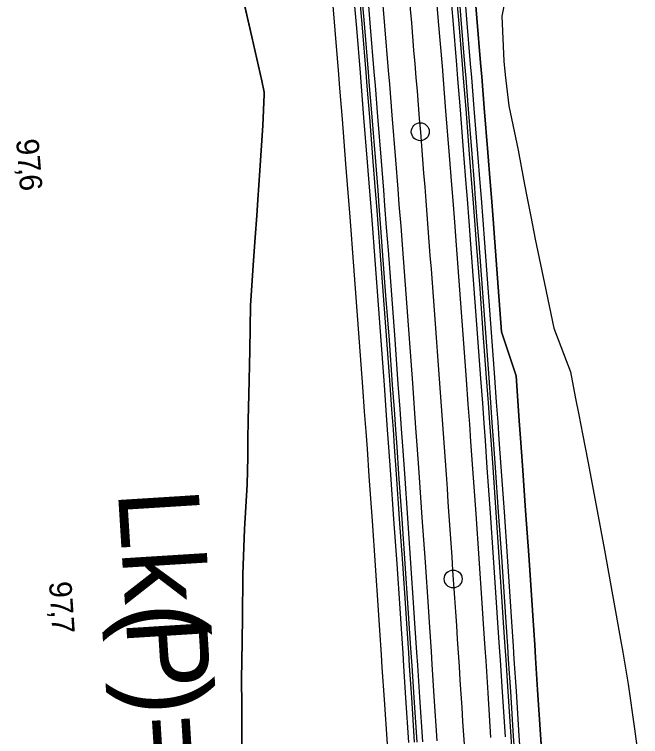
# Model space of a CAD drawing. Extents: x -678487 to -674601, y -1104811 to -1093295.
# Drawn here: x -677608.1 to -677468.4, y -1094531.8 to -1094370.8 of the extents above; entities that cross this region are included whole.
import ezdxf

# ---------------------------------------------------------------- set-up
doc = ezdxf.new("R2010")
doc.units = 0
for name, color, linetype in [('SOxxxxxx_Koleje_param další_Popis10', 7, 'Continuous'), ('SOxxxxxx_Osa_bod_P', 7, 'Continuous'), ('SOxxxxxx_Staničení_Popis', 7, 'Continuous'), ('SOxxxxxx_ŽSp_hrana', 7, 'Continuous'), ('SOxxxxxx_ŽSp_odvodnění', 7, 'Continuous'), ('SOxxxxxx_ŽSp_zářez_hrana', 7, 'Continuous'), ('SOxxxxxx_ŽSp_zářez_plocha', 7, 'Continuous')]:
    doc.layers.add(name, color=color, linetype=linetype)

msp = doc.modelspace()

# ---------------------------------------------------------------- linework, layer by layer
at = {"layer": 'SOxxxxxx_Osa_bod_P'}
msp.add_open_spline([(-677520.55, -1094360.39), (-677517.78, -1094392.94), (-677512.67, -1094458.09), (-677506.24, -1094555.89), (-677500.39, -1094653.74), (-677496.83, -1094718.98), (-677495.03, -1094751.61)], degree=3, dxfattribs=at)
at = {"layer": 'SOxxxxxx_Staničení_Popis'}
for p, q in [((-677517.54, -1094396.91), (-677517.54, -1094396.91)), ((-677510.2, -1094496.64), (-677510.2, -1094496.64))]:
    msp.add_line(p, q, dxfattribs=at)
for centre in [(-677517.54, -1094396.91), (-677510.2, -1094496.64)]:
    msp.add_circle(centre, 2, dxfattribs=at)
at = {"layer": 'SOxxxxxx_ŽSp_hrana'}
for p, q in [((-677526.33, -1094363.35), (-677525.49, -1094373.31)), ((-677525.49, -1094373.31), (-677524.67, -1094383.27)), ((-677524.67, -1094383.27), (-677524.42, -1094386.32)), ((-677524.42, -1094386.32), (-677523.86, -1094393.22)), ((-677523.86, -1094393.22), (-677523.07, -1094403.18)), ((-677523.07, -1094403.18), (-677522.56, -1094409.7)), ((-677522.56, -1094409.7), (-677522.29, -1094413.14)), ((-677522.29, -1094413.14), (-677521.91, -1094418)), ((-677521.91, -1094418), (-677521.52, -1094423.11)), ((-677521.52, -1094423.11), (-677520.77, -1094433.07)), ((-677520.77, -1094433.07), (-677520.03, -1094443.03)), ((-677520.03, -1094443.03), (-677519.3, -1094453)), ((-677519.3, -1094453), (-677518.89, -1094458.53)), ((-677518.89, -1094458.53), (-677518.58, -1094462.96)), ((-677518.58, -1094462.96), (-677518.3, -1094466.83)), ((-677518.3, -1094466.83), (-677517.87, -1094472.93)), ((-677517.87, -1094472.93), (-677517.17, -1094482.9)), ((-677517.17, -1094482.9), (-677516.48, -1094492.87)), ((-677516.48, -1094492.87), (-677515.81, -1094502.84)), ((-677515.81, -1094502.84), (-677515.5, -1094507.38)), ((-677515.5, -1094507.38), (-677515.14, -1094512.81)), ((-677515.14, -1094512.81), (-677514.95, -1094515.69)), ((-677514.95, -1094515.69), (-677514.48, -1094522.78)), ((-677514.48, -1094522.78), (-677513.83, -1094532.75))]:
    msp.add_line(p, q, dxfattribs=at)
msp.add_lwpolyline([(-677514.35, -1094362.34), (-677513.52, -1094372.31), (-677512.69, -1094382.29), (-677512.44, -1094385.35), (-677511.88, -1094392.26), (-677511.09, -1094402.24), (-677510.57, -1094408.77), (-677510.31, -1094412.22), (-677509.93, -1094417.08), (-677509.54, -1094422.2), (-677508.78, -1094432.18), (-677508.04, -1094442.16), (-677507.31, -1094452.14), (-677506.9, -1094457.68), (-677506.59, -1094462.12), (-677506.31, -1094466), (-677505.88, -1094472.11), (-677505.18, -1094482.09), (-677504.49, -1094492.07), (-677503.81, -1094502.06), (-677503.51, -1094506.61), (-677503.14, -1094512.04), (-677502.95, -1094514.93), (-677502.49, -1094522.03), (-677501.84, -1094532.02)], dxfattribs=at)
at = {"layer": 'SOxxxxxx_ŽSp_odvodnění'}
for p, q in [((-677509.87, -1094361.96), (-677509.03, -1094371.94)), ((-677509.32, -1094361.91), (-677508.48, -1094371.89)), ((-677531.36, -1094363.78), (-677530.53, -1094373.73)), ((-677530.81, -1094363.73), (-677529.98, -1094373.68)), ((-677509.03, -1094371.94), (-677508.21, -1094381.92)), ((-677508.48, -1094371.89), (-677507.66, -1094381.88)), ((-677530.53, -1094373.73), (-677529.71, -1094383.68)), ((-677529.98, -1094373.68), (-677529.16, -1094383.63)), ((-677508.21, -1094381.92), (-677507.96, -1094384.99)), ((-677507.66, -1094381.88), (-677507.41, -1094384.94)), ((-677529.71, -1094383.68), (-677529.46, -1094386.73)), ((-677529.16, -1094383.63), (-677528.91, -1094386.69)), ((-677507.96, -1094384.99), (-677507.4, -1094391.9)), ((-677507.41, -1094384.94), (-677506.85, -1094391.86)), ((-677529.46, -1094386.73), (-677528.9, -1094393.63)), ((-677528.91, -1094386.69), (-677528.35, -1094393.58)), ((-677507.4, -1094391.9), (-677506.6, -1094401.89)), ((-677506.85, -1094391.86), (-677506.05, -1094401.85)), ((-677528.35, -1094393.58), (-677527.56, -1094403.54)), ((-677528.9, -1094393.63), (-677528.1, -1094403.58)), ((-677506.6, -1094401.89), (-677506.09, -1094408.42)), ((-677506.05, -1094401.85), (-677505.54, -1094408.38)), ((-677528.1, -1094403.58), (-677527.59, -1094410.09)), ((-677527.56, -1094403.54), (-677527.04, -1094410.05)), ((-677506.09, -1094408.42), (-677505.82, -1094411.87)), ((-677505.54, -1094408.38), (-677505.27, -1094411.83)), ((-677527.59, -1094410.09), (-677527.32, -1094413.53)), ((-677527.04, -1094410.05), (-677526.78, -1094413.49)), ((-677505.82, -1094411.87), (-677505.44, -1094416.74)), ((-677505.27, -1094411.83), (-677504.89, -1094416.7)), ((-677527.32, -1094413.53), (-677526.95, -1094418.38)), ((-677526.78, -1094413.49), (-677526.4, -1094418.34)), ((-677505.44, -1094416.74), (-677505.05, -1094421.86)), ((-677504.89, -1094416.7), (-677504.5, -1094421.82)), ((-677526.95, -1094418.38), (-677526.56, -1094423.49)), ((-677526.4, -1094418.34), (-677526.01, -1094423.44)), ((-677505.05, -1094421.86), (-677504.29, -1094431.85)), ((-677504.5, -1094421.82), (-677503.74, -1094431.81)), ((-677526.56, -1094423.49), (-677525.8, -1094433.44)), ((-677526.01, -1094423.44), (-677525.26, -1094433.4)), ((-677504.29, -1094431.85), (-677503.55, -1094441.83)), ((-677503.74, -1094431.81), (-677503, -1094441.79)), ((-677525.8, -1094433.44), (-677525.06, -1094443.4)), ((-677525.26, -1094433.4), (-677524.51, -1094443.36)), ((-677503.55, -1094441.83), (-677502.82, -1094451.82)), ((-677503, -1094441.79), (-677502.27, -1094451.78)), ((-677525.06, -1094443.4), (-677524.33, -1094453.36)), ((-677524.51, -1094443.36), (-677523.78, -1094453.32)), ((-677502.82, -1094451.82), (-677502.42, -1094457.36)), ((-677502.27, -1094451.78), (-677501.87, -1094457.32)), ((-677524.33, -1094453.36), (-677523.93, -1094458.88)), ((-677523.78, -1094453.32), (-677523.38, -1094458.84)), ((-677502.42, -1094457.36), (-677502.1, -1094461.81)), ((-677501.87, -1094457.32), (-677501.55, -1094461.77)), ((-677523.93, -1094458.88), (-677523.61, -1094463.32)), ((-677523.38, -1094458.84), (-677523.07, -1094463.28)), ((-677502.1, -1094461.81), (-677501.82, -1094465.69)), ((-677501.55, -1094461.77), (-677501.27, -1094465.65)), ((-677523.61, -1094463.32), (-677523.34, -1094467.18)), ((-677523.07, -1094463.28), (-677522.79, -1094467.14)), ((-677501.82, -1094465.69), (-677501.39, -1094471.8)), ((-677501.27, -1094465.65), (-677500.84, -1094471.76)), ((-677523.34, -1094467.18), (-677522.91, -1094473.28)), ((-677522.79, -1094467.14), (-677522.36, -1094473.24)), ((-677501.39, -1094471.8), (-677500.69, -1094481.79)), ((-677500.84, -1094471.76), (-677500.14, -1094481.75)), ((-677522.91, -1094473.28), (-677522.21, -1094483.24)), ((-677522.36, -1094473.24), (-677521.66, -1094483.2)), ((-677500.69, -1094481.79), (-677500, -1094491.78)), ((-677500.14, -1094481.75), (-677499.45, -1094491.74)), ((-677522.21, -1094483.24), (-677521.52, -1094493.2)), ((-677521.66, -1094483.2), (-677520.97, -1094493.16)), ((-677500, -1094491.78), (-677499.32, -1094501.77)), ((-677499.45, -1094491.74), (-677498.77, -1094501.73)), ((-677521.52, -1094493.2), (-677520.85, -1094503.16)), ((-677520.97, -1094493.16), (-677520.3, -1094503.13)), ((-677499.32, -1094501.77), (-677499.02, -1094506.32)), ((-677498.77, -1094501.73), (-677498.47, -1094506.28)), ((-677520.85, -1094503.16), (-677520.54, -1094507.7)), ((-677520.3, -1094503.13), (-677519.99, -1094507.67)), ((-677499.02, -1094506.32), (-677498.65, -1094511.76)), ((-677498.47, -1094506.28), (-677498.11, -1094511.72)), ((-677520.54, -1094507.7), (-677520.18, -1094513.13)), ((-677519.99, -1094507.67), (-677519.63, -1094513.09)), ((-677498.65, -1094511.76), (-677498.46, -1094514.65)), ((-677498.11, -1094511.72), (-677497.91, -1094514.61)), ((-677520.18, -1094513.13), (-677519.99, -1094516.01)), ((-677519.63, -1094513.09), (-677519.44, -1094515.98)), ((-677519.44, -1094515.98), (-677518.97, -1094523.06)), ((-677498.46, -1094514.65), (-677497.99, -1094521.75)), ((-677497.91, -1094514.61), (-677497.45, -1094521.71)), ((-677519.99, -1094516.01), (-677519.52, -1094523.1)), ((-677497.99, -1094521.75), (-677497.34, -1094531.74)), ((-677497.45, -1094521.71), (-677496.8, -1094531.71)), ((-677519.52, -1094523.1), (-677518.87, -1094533.06)), ((-677518.97, -1094523.06), (-677518.33, -1094533.03)), ((-677497.34, -1094531.74), (-677496.7, -1094541.73)), ((-677496.8, -1094531.71), (-677496.15, -1094541.7))]:
    msp.add_line(p, q, dxfattribs=at)
at = {"layer": 'SOxxxxxx_ŽSp_zářez_hrana'}
for p, q in [((-677497.32, -1094360.89), (-677499.33, -1094371.13)), ((-677511.14, -1094362.07), (-677510.31, -1094372.04)), ((-677508.05, -1094361.8), (-677507.21, -1094371.79)), ((-677505.73, -1094361.61), (-677504.9, -1094371.59)), ((-677529.54, -1094363.63), (-677528.7, -1094373.58)), ((-677557.32, -1094365.98), (-677555.12, -1094375.78)), ((-677510.31, -1094372.04), (-677509.48, -1094382.03)), ((-677507.21, -1094371.79), (-677506.38, -1094381.77)), ((-677504.9, -1094371.59), (-677504.07, -1094381.58)), ((-677499.33, -1094371.13), (-677498.89, -1094381.16)), ((-677528.7, -1094373.58), (-677527.88, -1094383.53)), ((-677555.12, -1094375.78), (-677552.89, -1094385.57)), ((-677509.48, -1094382.03), (-677509.23, -1094385.09)), ((-677506.38, -1094381.77), (-677506.13, -1094384.84)), ((-677504.07, -1094381.58), (-677503.82, -1094384.65)), ((-677498.89, -1094381.16), (-677498.64, -1094384.23)), ((-677527.88, -1094383.53), (-677527.63, -1094386.58)), ((-677509.23, -1094385.09), (-677508.67, -1094392.01)), ((-677506.13, -1094384.84), (-677505.57, -1094391.76)), ((-677503.82, -1094384.65), (-677503.26, -1094391.57)), ((-677498.64, -1094384.23), (-677497.77, -1094391.13)), ((-677552.89, -1094385.57), (-677552.33, -1094388.12)), ((-677527.63, -1094386.58), (-677527.07, -1094393.48)), ((-677552.34, -1094388.59), (-677552.65, -1094395.53)), ((-677552.33, -1094388.12), (-677552.34, -1094388.59)), ((-677508.67, -1094392.01), (-677507.88, -1094401.99)), ((-677505.57, -1094391.76), (-677504.78, -1094401.74)), ((-677503.26, -1094391.57), (-677502.46, -1094401.56)), ((-677497.77, -1094391.13), (-677495.73, -1094401.03)), ((-677527.07, -1094393.48), (-677526.28, -1094403.44)), ((-677552.65, -1094395.53), (-677553.3, -1094405.56)), ((-677502.46, -1094401.56), (-677501.95, -1094408.1)), ((-677495.73, -1094401.03), (-677494.48, -1094407.52)), ((-677507.88, -1094401.99), (-677507.36, -1094408.52)), ((-677504.78, -1094401.74), (-677504.26, -1094408.28)), ((-677526.28, -1094403.44), (-677525.77, -1094409.95)), ((-677553.3, -1094405.56), (-677553.75, -1094412.12)), ((-677501.95, -1094408.1), (-677501.68, -1094411.55)), ((-677494.48, -1094407.52), (-677493.82, -1094410.95)), ((-677507.36, -1094408.52), (-677507.1, -1094411.97)), ((-677504.26, -1094408.28), (-677503.99, -1094411.73)), ((-677525.77, -1094409.95), (-677525.5, -1094413.39)), ((-677493.82, -1094410.95), (-677492.89, -1094415.78)), ((-677553.75, -1094412.12), (-677554.01, -1094415.59)), ((-677507.1, -1094411.97), (-677506.72, -1094416.84)), ((-677503.99, -1094411.73), (-677503.62, -1094416.6)), ((-677501.68, -1094411.55), (-677501.3, -1094416.42)), ((-677525.5, -1094413.39), (-677525.12, -1094418.24)), ((-677554.01, -1094415.59), (-677554.38, -1094420.48)), ((-677492.89, -1094415.78), (-677491.92, -1094420.87)), ((-677506.72, -1094416.84), (-677506.33, -1094421.96)), ((-677503.62, -1094416.6), (-677503.22, -1094421.72)), ((-677501.3, -1094416.42), (-677500.91, -1094421.55)), ((-677525.12, -1094418.24), (-677524.73, -1094423.35)), ((-677554.38, -1094420.48), (-677554.77, -1094425.62)), ((-677491.92, -1094420.87), (-677489.85, -1094430.78)), ((-677506.33, -1094421.96), (-677505.57, -1094431.94)), ((-677503.22, -1094421.72), (-677502.47, -1094431.71)), ((-677500.91, -1094421.55), (-677500.15, -1094431.54)), ((-677524.73, -1094423.35), (-677523.98, -1094433.31)), ((-677554.77, -1094425.62), (-677555.44, -1094435.64)), ((-677505.57, -1094431.94), (-677504.83, -1094441.93)), ((-677502.47, -1094431.71), (-677501.72, -1094441.7)), ((-677500.15, -1094431.54), (-677499.41, -1094441.53)), ((-677489.85, -1094430.78), (-677487.75, -1094440.69)), ((-677523.98, -1094433.31), (-677523.24, -1094443.27)), ((-677555.44, -1094435.64), (-677555.57, -1094445.62)), ((-677501.72, -1094441.7), (-677500.99, -1094451.69)), ((-677499.41, -1094441.53), (-677496.18, -1094451.35)), ((-677487.75, -1094440.69), (-677484.05, -1094450.48)), ((-677523.24, -1094443.27), (-677522.51, -1094453.23)), ((-677504.83, -1094441.93), (-677504.09, -1094451.91)), ((-677555.57, -1094445.62), (-677555.78, -1094455.6)), ((-677496.18, -1094451.35), (-677495.78, -1094456.9)), ((-677484.05, -1094450.48), (-677482.97, -1094455.99)), ((-677504.09, -1094451.91), (-677503.69, -1094457.45)), ((-677500.99, -1094451.69), (-677500.59, -1094457.23)), ((-677522.51, -1094453.23), (-677522.11, -1094458.75)), ((-677555.78, -1094455.6), (-677555.89, -1094461.14)), ((-677482.97, -1094455.99), (-677482.09, -1094460.41)), ((-677503.69, -1094457.45), (-677503.37, -1094461.9)), ((-677500.59, -1094457.23), (-677500.27, -1094461.68)), ((-677495.78, -1094456.9), (-677495.46, -1094461.35)), ((-677522.11, -1094458.75), (-677521.79, -1094463.19)), ((-677555.89, -1094461.14), (-677555.97, -1094465.58)), ((-677482.09, -1094460.41), (-677481.33, -1094464.27)), ((-677503.37, -1094461.9), (-677503.1, -1094465.78)), ((-677500.27, -1094461.68), (-677499.99, -1094465.56)), ((-677495.46, -1094461.35), (-677495.19, -1094465.23)), ((-677521.79, -1094463.19), (-677521.51, -1094467.06)), ((-677481.33, -1094464.27), (-677480.16, -1094470.34)), ((-677555.97, -1094465.58), (-677556.03, -1094469.45)), ((-677503.1, -1094465.78), (-677502.66, -1094471.89)), ((-677499.99, -1094465.56), (-677499.56, -1094471.67)), ((-677495.19, -1094465.23), (-677494.75, -1094471.34)), ((-677521.51, -1094467.06), (-677521.08, -1094473.15)), ((-677556.03, -1094469.45), (-677556.16, -1094475.56)), ((-677480.16, -1094470.34), (-677478.32, -1094480.28)), ((-677502.66, -1094471.89), (-677501.97, -1094481.87)), ((-677499.56, -1094471.67), (-677498.86, -1094481.67)), ((-677494.75, -1094471.34), (-677494.05, -1094481.34)), ((-677521.08, -1094473.15), (-677520.38, -1094483.11)), ((-677556.16, -1094475.56), (-677556.71, -1094485.56)), ((-677478.32, -1094480.28), (-677476.47, -1094490.22)), ((-677501.97, -1094481.87), (-677501.28, -1094491.86)), ((-677498.86, -1094481.67), (-677498.17, -1094491.66)), ((-677494.05, -1094481.34), (-677493.36, -1094491.34)), ((-677520.38, -1094483.11), (-677519.7, -1094493.08)), ((-677556.71, -1094485.56), (-677557.13, -1094495.55)), ((-677476.47, -1094490.22), (-677474.66, -1094500.17)), ((-677498.17, -1094491.66), (-677497.5, -1094501.65)), ((-677493.36, -1094491.34), (-677492.69, -1094501.34)), ((-677519.7, -1094493.08), (-677519.02, -1094503.05)), ((-677501.28, -1094491.86), (-677500.6, -1094501.85)), ((-677557.13, -1094495.55), (-677557.21, -1094505.52)), ((-677492.69, -1094501.34), (-677492.38, -1094505.89)), ((-677474.66, -1094500.17), (-677473.85, -1094504.7)), ((-677519.02, -1094503.05), (-677518.72, -1094507.59)), ((-677500.6, -1094501.85), (-677500.29, -1094506.4)), ((-677497.5, -1094501.65), (-677497.19, -1094506.2)), ((-677473.85, -1094504.7), (-677472.89, -1094510.12)), ((-677557.21, -1094505.52), (-677557.28, -1094510.07)), ((-677497.19, -1094506.2), (-677496.83, -1094511.64)), ((-677492.38, -1094505.89), (-677492.02, -1094511.34)), ((-677518.72, -1094507.59), (-677518.35, -1094513.01)), ((-677500.29, -1094506.4), (-677499.93, -1094511.84)), ((-677557.28, -1094510.07), (-677557.37, -1094515.5)), ((-677472.89, -1094510.12), (-677472.39, -1094512.99)), ((-677499.93, -1094511.84), (-677499.74, -1094514.73)), ((-677496.83, -1094511.64), (-677496.64, -1094514.53)), ((-677492.02, -1094511.34), (-677491.83, -1094514.23)), ((-677518.35, -1094513.01), (-677518.16, -1094515.89)), ((-677491.83, -1094514.23), (-677491.36, -1094521.33)), ((-677472.39, -1094512.99), (-677471.15, -1094520.07)), ((-677557.37, -1094515.5), (-677557.41, -1094518.38)), ((-677518.16, -1094515.89), (-677517.7, -1094522.98)), ((-677499.74, -1094514.73), (-677499.27, -1094521.83)), ((-677496.64, -1094514.53), (-677496.17, -1094521.63)), ((-677557.41, -1094518.38), (-677557.37, -1094525.46)), ((-677471.15, -1094520.07), (-677469.75, -1094530.04)), ((-677499.27, -1094521.83), (-677498.62, -1094531.82)), ((-677496.17, -1094521.63), (-677495.52, -1094531.63)), ((-677491.36, -1094521.33), (-677490.71, -1094531.33)), ((-677517.7, -1094522.98), (-677517.05, -1094532.95)), ((-677557.37, -1094525.46), (-677557.31, -1094535.42)), ((-677469.75, -1094530.04), (-677468.4, -1094540.02)), ((-677495.52, -1094531.63), (-677494.88, -1094541.62)), ((-677490.71, -1094531.33), (-677490.06, -1094541.33))]:
    msp.add_line(p, q, dxfattribs=at)
for points in [[(-677537.44, -1094364.3), (-677536.61, -1094374.23), (-677535.78, -1094384.17), (-677535.54, -1094387.23), (-677534.98, -1094394.12), (-677534.19, -1094404.06), (-677533.68, -1094410.56), (-677533.41, -1094414), (-677533.03, -1094418.85), (-677532.64, -1094423.95), (-677531.89, -1094433.89), (-677531.15, -1094443.84), (-677530.42, -1094453.79), (-677530.02, -1094459.31), (-677529.7, -1094463.74), (-677529.42, -1094467.6), (-677528.99, -1094473.69), (-677528.3, -1094483.65), (-677527.61, -1094493.6), (-677526.93, -1094503.56), (-677526.63, -1094508.09), (-677526.27, -1094513.52), (-677526.08, -1094516.4), (-677525.61, -1094523.48), (-677524.96, -1094533.44)], [(-677532.64, -1094363.89), (-677531.8, -1094373.83), (-677530.98, -1094383.78), (-677530.73, -1094386.84), (-677530.17, -1094393.73), (-677529.38, -1094403.68), (-677528.87, -1094410.19), (-677528.6, -1094413.63), (-677528.23, -1094418.48), (-677527.83, -1094423.58), (-677527.08, -1094433.54), (-677526.34, -1094443.49), (-677525.61, -1094453.45), (-677525.21, -1094458.97), (-677524.89, -1094463.4), (-677524.61, -1094467.27), (-677524.18, -1094473.36), (-677523.49, -1094483.32), (-677522.8, -1094493.28), (-677522.12, -1094503.25), (-677521.82, -1094507.79), (-677521.46, -1094513.21), (-677521.27, -1094516.09), (-677520.8, -1094523.18), (-677520.15, -1094533.14)]]:
    msp.add_lwpolyline(points, dxfattribs=at)
at = {"layer": 'SOxxxxxx_ŽSp_zářez_plocha'}
for points in [[(-677497.32, -1094360.89), (-677499.33, -1094371.13), (-677498.89, -1094381.16), (-677498.64, -1094384.23), (-677497.77, -1094391.13), (-677495.73, -1094401.03), (-677494.48, -1094407.52), (-677493.82, -1094410.95), (-677492.89, -1094415.78), (-677491.92, -1094420.87), (-677489.85, -1094430.78), (-677487.75, -1094440.69), (-677484.05, -1094450.48), (-677482.97, -1094455.99), (-677482.09, -1094460.41), (-677481.33, -1094464.27), (-677480.16, -1094470.34), (-677478.32, -1094480.28), (-677476.47, -1094490.22), (-677474.66, -1094500.17), (-677473.85, -1094504.7), (-677472.89, -1094510.12), (-677472.39, -1094512.99), (-677471.15, -1094520.07), (-677469.75, -1094530.04), (-677468.4, -1094540.02)], [(-677490.06, -1094541.33), (-677490.71, -1094531.33), (-677491.36, -1094521.33), (-677491.83, -1094514.23), (-677492.02, -1094511.34), (-677492.38, -1094505.89), (-677492.69, -1094501.34), (-677493.36, -1094491.34), (-677494.05, -1094481.34), (-677494.75, -1094471.34), (-677495.19, -1094465.23), (-677495.46, -1094461.35), (-677495.78, -1094456.9), (-677496.18, -1094451.35), (-677499.41, -1094441.53), (-677500.15, -1094431.54), (-677500.91, -1094421.55), (-677501.3, -1094416.42), (-677501.68, -1094411.55), (-677501.95, -1094408.1), (-677502.46, -1094401.56), (-677503.26, -1094391.57), (-677503.82, -1094384.65), (-677504.07, -1094381.58), (-677504.9, -1094371.59), (-677505.73, -1094361.61)], [(-677537.44, -1094364.3), (-677536.61, -1094374.23), (-677535.78, -1094384.17), (-677535.54, -1094387.23), (-677534.98, -1094394.12), (-677534.19, -1094404.06), (-677533.68, -1094410.56), (-677533.41, -1094414), (-677533.03, -1094418.85), (-677532.64, -1094423.95), (-677531.89, -1094433.89), (-677531.15, -1094443.84), (-677530.42, -1094453.79), (-677530.02, -1094459.31), (-677529.7, -1094463.74), (-677529.42, -1094467.6), (-677528.99, -1094473.69), (-677528.3, -1094483.65), (-677527.61, -1094493.6), (-677526.93, -1094503.56), (-677526.63, -1094508.09), (-677526.27, -1094513.52), (-677526.08, -1094516.4), (-677525.61, -1094523.48), (-677524.96, -1094533.44)], [(-677557.31, -1094535.42), (-677557.37, -1094525.46), (-677557.41, -1094518.38), (-677557.37, -1094515.5), (-677557.28, -1094510.07), (-677557.21, -1094505.52), (-677557.13, -1094495.55), (-677556.71, -1094485.56), (-677556.16, -1094475.56), (-677556.03, -1094469.45), (-677555.97, -1094465.58), (-677555.89, -1094461.14), (-677555.78, -1094455.6), (-677555.57, -1094445.62), (-677555.44, -1094435.64), (-677554.77, -1094425.62), (-677554.38, -1094420.48), (-677554.01, -1094415.59), (-677553.75, -1094412.12), (-677553.3, -1094405.56), (-677552.65, -1094395.53), (-677552.34, -1094388.59), (-677552.33, -1094388.12), (-677552.89, -1094385.57), (-677555.12, -1094375.78), (-677557.32, -1094365.98)]]:
    msp.add_lwpolyline(points, dxfattribs=at)

# ---------------------------------------------------------------- texts
at = {"layer": 'SOxxxxxx_Koleje_param další_Popis10'}
for s, p in [('Lk(', (-677584.99, -1094477.06)), ('P', (-677583.2, -1094505.65)), (')=', (-677582.34, -1094519.37))]:
    msp.add_text(s, height=18, rotation=273.5909, dxfattribs=at).set_placement(p)
at = {"layer": 'SOxxxxxx_Staničení_Popis'}
for s, rotation, p in [('97', 274.5637, (-677607.69, -1094398.65)), (',', 274.5637, (-677607.18, -1094405)), ('6', 274.5637, (-677607.05, -1094406.59)), ('97', 273.8876, (-677600.36, -1094497.32)), (',', 273.8876, (-677599.93, -1094503.67)), ('7', 273.8876, (-677599.82, -1094505.27))]:
    msp.add_text(s, height=5, rotation=rotation, dxfattribs=at).set_placement(p)

doc.saveas('drawing.dxf')
